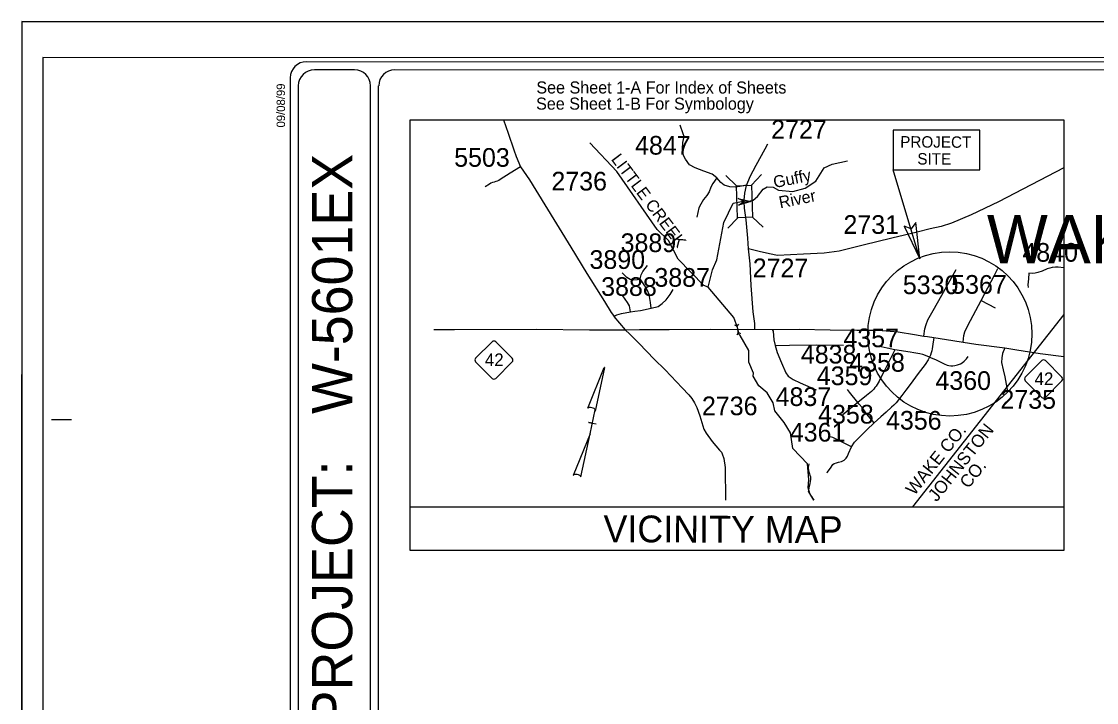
# Model space of a CAD drawing. Extents: x 2110629 to 2114002, y 669321 to 671542.
# Drawn here: x 2110629 to 2111780, y 670813 to 671542 of the extents above; entities that cross this region are included whole.
import ezdxf

# ---------------------------------------------------------------- set-up
doc = ezdxf.new("R2010")
doc.units = 0
for name, color, linetype in [('Default', 7, 'Continuous'), ('Default Symbol Cogo Number', 7, 'Continuous'), ('Exist Building', 7, 'Continuous'), ('Exist Building Leader', 7, 'Continuous'), ('Exist Other Culture Area Outline', 7, 'Continuous'), ('Exist Roads Curbs', 7, 'Continuous'), ('Exist Roads Curbs Text', 7, 'Continuous'), ('Exist Roads EOP Other Text', 7, 'Continuous'), ('Exist Structure Minor Catch Basin', 7, 'Continuous'), ('Exist Structure Minor Footbridge', 7, 'Continuous'), ('Exist Utilities Telephone Test Hole SUE LOS A Text', 7, 'Continuous'), ('Exist Utilities TV Hand Hole CELL', 7, 'Continuous'), ('Exist Utilities Water Test Hole SUE LOS A Text', 7, 'Continuous')]:
    doc.layers.add(name, color=color, linetype=linetype)

msp = doc.modelspace()

# ---------------------------------------------------------------- linework, layer by layer
at = {"layer": 'Default'}
for p, q in [((2111383, 671377.1), (2111394.4, 671366.3)), ((2111421.2, 671378.3), (2111410.5, 671366.8)), ((2111395.8, 671332.1), (2111385.1, 671320.7)), ((2111411.5, 671332.6), (2111422.9, 671321.9)), ((2111392.5, 671217.3), (2111395, 671215.9)), ((2111396.6, 671218.3), (2111395, 671215.9)), ((2111395, 671215.9), (2111396.8, 671209.2)), ((2111395.2, 671206.8), (2111396.8, 671209.2)), ((2111399.3, 671207.8), (2111396.8, 671209.2))]:
    msp.add_line(p, q, dxfattribs=at)
for points in [[(2111364.3, 671257.6), (2111359.4, 671259.5), (2111332, 671287.6), (2111321.7, 671307.6), (2111309.7, 671319.3), (2111266.2, 671381.5), (2111237.4, 671412.2)], [(2111390.9, 671347.7), (2111398.2, 671349.2), (2111399.9, 671349.4), (2111402.8, 671349.3), (2111404.4, 671349.1), (2111412.4, 671350.9), (2111417, 671354.7), (2111423, 671362.5), (2111427.4, 671365.1), (2111433.7, 671364.8), (2111439.3, 671361.6), (2111454.9, 671360.2), (2111468.2, 671363.7), (2111479.4, 671371.1), (2111488.2, 671385.6), (2111496.8, 671389.5), (2111513.2, 671392.8)], [(2111402.8, 671349.3), (2111402.8, 671351), (2111403.4, 671358.5), (2111405.1, 671366.6)], [(2111364.3, 671257.6), (2111368.7, 671276.1), (2111373.4, 671287), (2111380.8, 671327.1), (2111390.9, 671347.7)], [(2111477.2, 671029.9), (2111472.9, 671036.8), (2111471.3, 671042.9), (2111471.8, 671052), (2111470.5, 671068.8), (2111455, 671085), (2111452.3, 671102), (2111445.5, 671113), (2111435.5, 671125.3), (2111433.9, 671133.9), (2111427.5, 671144.8), (2111418.4, 671152), (2111412.4, 671162.4), (2111412.6, 671165.8), (2111407.8, 671177.5), (2111407.6, 671190.1), (2111398.6, 671206), (2111396.8, 671207.7), (2111396.4, 671208.7), (2111396.3, 671210.8), (2111395.9, 671212.5), (2111395.4, 671214.5), (2111391.8, 671225.2), (2111364.3, 671257.6)], [(2111471.9, 671068.5), (2111471.5, 671067), (2111471.2, 671065.1), (2111471.1, 671064), (2111471.5, 671061.4), (2111472, 671060), (2111472.6, 671058.1), (2111473.2, 671056.6), (2111473.7, 671054.9), (2111473.6, 671052.2), (2111473.3, 671049.8), (2111473, 671047.6), (2111472.6, 671045.7), (2111472, 671043.3), (2111471.5, 671039.9), (2111471.4, 671039.7), (2111471.8, 671037.9), (2111472.6, 671036.8), (2111473.8, 671035.1), (2111475.1, 671033.6), (2111476, 671031.9), (2111477.2, 671029.9)]]:
    msp.add_lwpolyline(points, dxfattribs=at)
for points in [[(2111410.5, 671366.8), (2111411.5, 671332.6), (2111395.5, 671332.1), (2111394.4, 671366.3)], [(2111396.2, 671352.6), (2111409.7, 671349.5), (2111396.5, 671345.4), (2111402.8, 671349.3)]]:
    msp.add_lwpolyline(points, close=True, dxfattribs=at)
at = {"layer": 'Default Symbol Cogo Number'}
for p, q in [((2111590.8, 671288.1), (2111562.2, 671383.3)), ((2111745, 671031.5), (2111745, 671028.9)), ((2111045, 671022.6), (2111745, 671022.6))]:
    msp.add_line(p, q, dxfattribs=at)
msp.add_lwpolyline([(2111745, 671028.9), (2111745, 670975.8), (2111045, 670975.8), (2111045, 671436.7), (2111745, 671436.7), (2111745, 671031.5)], dxfattribs=at)
for points in [[(2111562.2, 671383.3), (2111655.1, 671383.3), (2111655.1, 671425.9), (2111562.2, 671425.9)], [(2111573.9, 671322.9), (2111590.8, 671288.1), (2111586.7, 671326.8), (2111581.5, 671320.2)]]:
    msp.add_lwpolyline(points, close=True, dxfattribs=at)
msp.add_circle((2111622.9, 671207.7), 87.9, dxfattribs=at)
at = {"layer": 'Exist Building'}
for p, q in [((2111115.2, 671181.6), (2111132.9, 671199.3)), ((2111136.7, 671199.3), (2111154.4, 671181.6)), ((2111114.4, 671179.9), (2111114.4, 671179.9)), ((2111132.9, 671160.1), (2111115.2, 671177.8)), ((2111154.4, 671177.8), (2111136.7, 671160.1)), ((2111703.7, 671161.4), (2111721.5, 671179.1)), ((2111725.3, 671179.1), (2111743, 671161.3)), ((2111702.9, 671159.6), (2111702.9, 671159.6)), ((2111721.4, 671139.8), (2111703.7, 671157.6)), ((2111743, 671157.5), (2111725.2, 671139.8))]:
    msp.add_line(p, q, dxfattribs=at)
for centre, start, end in [((2111134.8, 671197.4), 93.1291, 134.9188), ((2111134.8, 671197.4), 44.9188, 92.9952), ((2111117.1, 671179.7), 134.9188, 176.3258), ((2111152.5, 671179.7), 1.8482, 44.9188), ((2111117.1, 671179.7), 176.4784, 224.9188), ((2111152.5, 671179.7), 314.9188, 1.6571), ((2111723.4, 671177.2), 93.1291, 134.9188), ((2111723.4, 671177.2), 44.9188, 92.9952), ((2111134.8, 671162), 224.9188, 264.9661), ((2111134.8, 671162), 265.1003, 314.9188), ((2111705.6, 671159.5), 134.9188, 176.3258), ((2111705.6, 671159.5), 176.4784, 224.9188), ((2111741.1, 671159.4), 1.8482, 44.9188), ((2111741.1, 671159.4), 314.9188, 1.6571), ((2111723.3, 671141.7), 224.9188, 264.9661), ((2111723.3, 671141.7), 265.1003, 314.9188)]:
    msp.add_arc(centre, 2.69, start, end, dxfattribs=at)
at = {"layer": 'Exist Building Leader'}
for points in [[(2111070.3, 671212.5), (2111092.6, 671212.3), (2111180.2, 671212.6), (2111237.2, 671212.2), (2111275.3, 671212.2)], [(2111275.3, 671212.2), (2111290.6, 671212.3), (2111322.3, 671212.3), (2111367.2, 671212.6), (2111395.9, 671212.5), (2111414.2, 671212.6)], [(2111414.2, 671212.6), (2111432.7, 671212.5)], [(2111432.7, 671212.5), (2111461.6, 671212.6), (2111494.7, 671212.1), (2111523.3, 671211.8), (2111546.3, 671211.7), (2111567.6, 671209.8)], [(2111567.6, 671209.8), (2111585, 671207.1), (2111595.1, 671205.4)], [(2111595.1, 671205.4), (2111599.1, 671204.8), (2111605.9, 671203.8)], [(2111605.9, 671203.8), (2111626.3, 671200.7), (2111637.1, 671199)], [(2111637.1, 671199), (2111650.9, 671196.8), (2111681.8, 671192.7)], [(2111681.8, 671192.7), (2111694.7, 671190.7), (2111719.5, 671186.6), (2111745, 671183.4)]]:
    msp.add_lwpolyline(points, dxfattribs=at)
at = {"layer": 'Exist Roads Curbs'}
for q in [(2110628.9, 669648.7), (2113527.8, 671541.5)]:
    msp.add_line((2110629.2, 671542), q, dxfattribs=at)
at = {"layer": 'Exist Roads Curbs Text'}
for p, q in [((2111163.2, 671386.5), (2111152.3, 671379.9)), ((2111656.5, 671243.4), (2111671.3, 671235.6))]:
    msp.add_line(p, q, dxfattribs=at)
for points in [[(2111144.9, 671436.7), (2111149.9, 671422.6), (2111156.1, 671404.6), (2111158.7, 671397.5), (2111163.2, 671386.5)], [(2111373.5, 671374.7), (2111368.3, 671378.7), (2111359.6, 671381.9), (2111350.2, 671385.4), (2111344.3, 671388.8), (2111339.8, 671394.7), (2111337.6, 671398.7), (2111336.7, 671405.6), (2111337, 671412.7), (2111338.3, 671418.8), (2111337.5, 671421.7), (2111334.2, 671431)], [(2111405.1, 671366.6), (2111409.2, 671376.3), (2111415.7, 671388.4), (2111425.2, 671405.7), (2111428.2, 671411)], [(2111152.3, 671379.9), (2111141.5, 671372.8), (2111140, 671372), (2111138.3, 671371.2), (2111136.7, 671370.7), (2111135, 671370.2), (2111133.2, 671369.6), (2111131.5, 671368.9), (2111130, 671368), (2111125.4, 671365.1)], [(2111163.2, 671386.5), (2111172.8, 671372.5), (2111189.4, 671345.7), (2111217.1, 671300.4), (2111234.4, 671272.3), (2111253, 671242.4), (2111260.2, 671230.7), (2111263.7, 671226)], [(2111745, 671385.4), (2111675, 671349), (2111645.8, 671335.3), (2111624.6, 671326.2), (2111613.5, 671322.8), (2111601.8, 671320.1), (2111587.8, 671316.6), (2111560.7, 671310), (2111530.2, 671302.5), (2111504.3, 671296.4), (2111488.5, 671294.1), (2111466.4, 671292.9), (2111438.3, 671291.7)], [(2111373.5, 671374.7), (2111369.1, 671368.5), (2111367, 671364.6), (2111365.2, 671359.6), (2111362.8, 671355.7), (2111359.2, 671351.6), (2111356.2, 671346.6), (2111354.1, 671342.5), (2111352, 671332.7)], [(2111405.1, 671366.6), (2111403.3, 671366.5), (2111398.2, 671365.4), (2111393.1, 671364.8), (2111387.2, 671365.2), (2111381.4, 671367), (2111377.9, 671369.7), (2111373.5, 671374.7)], [(2111407.4, 671298.6), (2111406.5, 671310.3), (2111404.9, 671329.9), (2111403.2, 671342.3), (2111402.8, 671349.3)], [(2111438.3, 671291.7), (2111429.8, 671293.3), (2111418.9, 671296), (2111407.4, 671298.6)], [(2111414.2, 671212.6), (2111414, 671218.9), (2111412.5, 671231.2), (2111410.3, 671259.4), (2111409.2, 671282.7), (2111407.4, 671298.6)], [(2111291.3, 671266.6), (2111288, 671265.5), (2111284.3, 671265.3), (2111280.7, 671265.9), (2111277.2, 671268.1), (2111272.2, 671273.1)], [(2111291.3, 671266.6), (2111292.5, 671271.1), (2111294.3, 671274.4), (2111299.2, 671281)], [(2111595.1, 671205.4), (2111596.2, 671213), (2111597.5, 671217.7), (2111599.5, 671222.7), (2111603.6, 671230.4), (2111611.1, 671243.5), (2111629.7, 671276.8)], [(2111656.5, 671243.4), (2111670.6, 671270.4), (2111674.4, 671277.7)], [(2111745, 671278.4), (2111739.1, 671279), (2111738.3, 671279.1), (2111736, 671279), (2111732.6, 671278.7), (2111730, 671278.2), (2111727.2, 671277.3), (2111721.8, 671274.9), (2111717.3, 671273.3), (2111714.3, 671272.7), (2111711, 671272.4), (2111707.6, 671272.6)], [(2111303.2, 671235.2), (2111302.4, 671241.3), (2111301.1, 671249.9), (2111299.2, 671254.1), (2111296.2, 671259.2), (2111291.3, 671266.6)], [(2111707.6, 671272.6), (2111707, 671266.8), (2111706.6, 671260.3), (2111706.7, 671257.3)], [(2111303.2, 671235.2), (2111310.5, 671237.2), (2111314.8, 671240.1), (2111319.2, 671244), (2111323.4, 671249.8), (2111326.6, 671255.4)], [(2111281, 671231.3), (2111279.9, 671237.7), (2111277.8, 671241.4), (2111272.7, 671248.6)], [(2111637.1, 671199), (2111638, 671206.1), (2111639.1, 671210.1), (2111640.7, 671213.7), (2111645.2, 671222), (2111656.5, 671243.4)], [(2111263.2, 671226.2), (2111266.4, 671228.1), (2111271.4, 671229.7), (2111281, 671231.3)], [(2111281, 671231.3), (2111285.6, 671232), (2111291.8, 671232.9), (2111303.2, 671235.2)], [(2111263.2, 671226.2), (2111275.3, 671212.2)], [(2111275.3, 671212.2), (2111280.3, 671207.4), (2111290.4, 671197.5), (2111306.4, 671180.8), (2111318, 671169.1), (2111336.3, 671150), (2111343.3, 671142.6), (2111346.7, 671138.4), (2111349.7, 671133.8), (2111352.1, 671128.9), (2111355.2, 671119.9), (2111359.4, 671105.9), (2111362, 671101.5), (2111368.6, 671092.7), (2111376.4, 671083.4), (2111378.3, 671081.1), (2111379.3, 671079.4), (2111381.1, 671074.3), (2111382.4, 671064.8), (2111382.6, 671029.9)], [(2111432.7, 671212.5), (2111433.9, 671210.5), (2111434.6, 671201.4), (2111435.8, 671195.2)], [(2111605.9, 671203.8), (2111604.5, 671194.4), (2111604.1, 671191.8), (2111603.6, 671189.6), (2111603, 671187.3), (2111602.1, 671184.8), (2111601.2, 671182.7)], [(2111435.8, 671195.2), (2111451.3, 671195.8), (2111480.7, 671196), (2111509, 671195.8)], [(2111435.8, 671195.2), (2111437.9, 671187.7), (2111442.7, 671176.9), (2111447.4, 671165.9), (2111449.7, 671162.3), (2111455.1, 671158.8), (2111462.5, 671155.4), (2111479.9, 671147.9)], [(2111563.9, 671190.8), (2111555.7, 671192.6), (2111549.5, 671193.8), (2111548.2, 671194.1)], [(2111681.8, 671192.7), (2111679.5, 671186.7), (2111678.6, 671182.2), (2111678.4, 671177.2), (2111680.2, 671169.3), (2111681.9, 671161.6), (2111684.6, 671146.1)], [(2111564.2, 671190.8), (2111558.5, 671179.2), (2111553.2, 671169.1), (2111549.5, 671161.9), (2111547.1, 671157), (2111545.2, 671153.7), (2111544, 671151.8), (2111542.7, 671150.2), (2111541.4, 671148.5), (2111538.9, 671146), (2111533.7, 671141.7), (2111524.4, 671134.3)], [(2111601.2, 671182.7), (2111599.7, 671180), (2111596.4, 671175), (2111589, 671165.2), (2111580.3, 671153.5), (2111575.8, 671147.6), (2111571.6, 671141.9), (2111567.8, 671137.1), (2111565.6, 671134.1), (2111562.9, 671131.3), (2111560.4, 671129.2), (2111554.8, 671124), (2111549, 671118.8), (2111542, 671112.4)], [(2111601.2, 671182.7), (2111596.8, 671184.7), (2111593.9, 671185.6), (2111590.7, 671186.4), (2111584.4, 671187.6), (2111580.5, 671188.3), (2111563.9, 671190.8)], [(2111601.2, 671182.7), (2111607.5, 671180.2), (2111612.6, 671177.7), (2111616.7, 671175.7), (2111620, 671174.3), (2111621.9, 671173.8), (2111623.9, 671173.5), (2111626, 671173.5), (2111628.3, 671173.8), (2111631.2, 671174.6), (2111634.2, 671175.8), (2111636, 671176.7), (2111638.2, 671178.5), (2111640.6, 671181), (2111642.7, 671183.7)], [(2111524.4, 671134.3), (2111515.4, 671145.2), (2111513.3, 671148.2)], [(2111524.4, 671134.3), (2111518.6, 671129.7), (2111512.5, 671124.6), (2111508.2, 671121.2)], [(2111542, 671112.4), (2111534.2, 671121.7), (2111528.9, 671128.8), (2111525.7, 671132.6), (2111524.4, 671134.3)], [(2111517.5, 671086.7), (2111521, 671091.9), (2111534.1, 671105), (2111542, 671112.4)], [(2111517.5, 671086.7), (2111497.6, 671096.8), (2111494.8, 671097.4)], [(2111491.4, 671059.2), (2111491.6, 671059.4), (2111495.1, 671064.1), (2111497.8, 671067.9), (2111499.2, 671068.9), (2111501.6, 671069.9), (2111503.8, 671070.4), (2111507.1, 671071.3), (2111509.7, 671072.7), (2111511.9, 671074.6), (2111513.5, 671076.7), (2111514.6, 671079.6), (2111517.5, 671086.7)]]:
    msp.add_lwpolyline(points, dxfattribs=at)
at = {"layer": 'Exist Roads EOP Other Text'}
msp.add_lwpolyline([(2110651.3, 669687.3), (2113519.8, 669686.8), (2113520.1, 671502.9), (2110651.6, 671503.4)], close=True, dxfattribs=at)
at = {"layer": 'Exist Structure Minor Catch Basin'}
for p, q in [((2111002.4, 669717.5), (2111002.7, 671473.1)), ((2111011.1, 670035.9), (2111011.3, 671473.1)), ((2110661, 671116), (2110682.5, 671116)), ((2110661, 671116), (2110682.5, 671116))]:
    msp.add_line(p, q, dxfattribs=at)
for points in [[(2113481.4, 671498.5), (2110933.9, 671499)], [(2110916.7, 671481.8), (2110916.4, 669708.9)], [(2110916.7, 671481.8), (2110916.4, 669708.9)], [(2110985.5, 671490.3), (2110942.5, 671490.4)], [(2113472.7, 671489.9), (2111028.6, 671490.3)], [(2110925.3, 671473.2), (2110925, 669717.5)]]:
    msp.add_lwpolyline(points, dxfattribs=at)
for centre, start, end in [((2110933.9, 671481.8), 89.9903, 179.9903), ((2110942.5, 671473.2), 89.9903, 179.9903), ((2110985.5, 671473.2), 359.9903, 89.9903), ((2111028.6, 671473.2), 89.9903, 179.9903)]:
    msp.add_arc(centre, 17.2, start, end, dxfattribs=at)
at = {"layer": 'Exist Structure Minor Footbridge'}
msp.add_line((2111745, 671228.6), (2111583.1, 671022.6), dxfattribs=at)
at = {"layer": 'Exist Utilities TV Hand Hole CELL'}
for p, q in [((2111235.2, 671128.2), (2111252.9, 671171.8)), ((2111253, 671171.8), (2111243, 671125)), ((2111253, 671171.8), (2111252.9, 671171.8)), ((2111253, 671171.8), (2111252.9, 671171.8)), ((2111237.8, 671100.8), (2111243.3, 671126.4)), ((2111243, 671125), (2111243.2, 671126.4)), ((2111236.3, 671113), (2111236.2, 671113)), ((2111236.3, 671113), (2111244.2, 671111.3)), ((2111239.8, 671112.2), (2111236.3, 671113)), ((2111237.8, 671100.8), (2111219.7, 671056.3)), ((2111228, 671054.8), (2111237.8, 671100.8))]:
    msp.add_line(p, q, dxfattribs=at)
for centre, start_param, end_param in [((2111239.1, 671126.8), 0.216388, 2.908219), ((2111223.9, 671055.3), 0.201328, 3.141593)]:
    msp.add_ellipse(centre, major_axis=(4.13, -0.91), ratio=0.461098, start_param=start_param, end_param=end_param, dxfattribs=at)
at = {"layer": 'Exist Utilities Water Test Hole SUE LOS A Text'}
msp.add_lwpolyline([(2113527.8, 671541.5), (2110629.2, 671542), (2110628.9, 669648.7), (2113527.5, 669648.2)], close=True, dxfattribs=at)

# ---------------------------------------------------------------- texts
at = {"layer": 'Default'}
for s, height, rotation, p in [('LITTLE CREEK', 12.762, 306.9522, (2111259.7, 671394.5)), ('Guffy', 12.76, 11.4692, (2111435.3, 671363.7)), ('River', 12.76, 11.4692, (2111441.3, 671342))]:
    msp.add_text(s, height=height, rotation=rotation, dxfattribs=at).set_placement(p)
at = {"layer": 'Default Symbol Cogo Number'}
for s, height, rotation, p in [('PROJECT', 12.2, 359.7111, (2111569.8, 671407.2)), ('SITE', 12.2, 359.7111, (2111588.1, 671389)), ('VICINITY MAP', 28.714, 359.7803, (2111252, 670984.8))]:
    msp.add_text(s, height=height, rotation=rotation, dxfattribs=at).set_placement(p)
at = {"layer": 'Exist Building'}
for p in [(2111125.1, 671173.3), (2111713.7, 671153)]:
    msp.add_text('42', height=13.5, rotation=359.9188, dxfattribs=at).set_placement(p)
at = {"layer": 'Exist Other Culture Area Outline'}
for s, p in [('2727', (2111431.6, 671416.6)), ('4847', (2111285.9, 671399.6)), ('5503', (2111092.2, 671386.6)), ('2736', (2111196.3, 671361.2)), ('2731', (2111509, 671314.8)), ('3889', (2111270.4, 671295.3)), ('3890', (2111237.1, 671277.3)), ('4840', (2111700.6, 671285)), ('2727', (2111411.9, 671268.4)), ('3887', (2111306.6, 671258.2)), ('3888', (2111249.6, 671248.4)), ('5330', (2111572.6, 671250.3)), ('5367', (2111624.4, 671250.7)), ('4357', (2111509, 671193.5)), ('4838', (2111463.4, 671176)), ('4358', (2111515.3, 671167.3)), ('4359', (2111480.5, 671152.9)), ('4360', (2111607.5, 671147.8)), ('4837', (2111436.4, 671130.6)), ('2735', (2111677.1, 671127.6)), ('2736', (2111357.5, 671120.7)), ('4358', (2111481.9, 671111.8)), ('4356', (2111554.6, 671105.3)), ('4361', (2111451.6, 671092.5))]:
    msp.add_text(s, height=20, rotation=359.932, dxfattribs=at).set_placement(p)
at = {"layer": 'Exist Structure Minor Catch Basin'}
for s, height, rotation, p in [('09/08/99', 9.04, 89.9903, (2110911.1, 671428.6)), ('See Sheet 1-A For Index of Sheets', 12.909, 359.9903, (2111180.2, 671465)), ('See Sheet 1-B For Symbology', 12.909, 359.9903, (2111179.9, 671447.7)), ('W-5601EX', 43.03, 89.9903, (2110983.1, 671122.1)), ('TIP PROJECT:', 43.031, 89.9903, (2110983, 670682.2))]:
    msp.add_text(s, height=height, rotation=rotation, dxfattribs=at).set_placement(p)
at = {"layer": 'Exist Structure Minor Footbridge'}
for s, p in [('JOHNSTON ', (2111608.8, 671027.3)), ('WAKE CO.', (2111585, 671034)), ('CO.', (2111642.8, 671041.4))]:
    msp.add_text(s, height=13.5, rotation=51.2991, dxfattribs=at).set_placement(p)
at = {"layer": 'Exist Utilities Telephone Test Hole SUE LOS A Text'}
msp.add_text('         WAKE COUNTY         ', height=51.637, rotation=359.9903, dxfattribs=at).set_placement((2111490, 671283.3))

doc.saveas('drawing.dxf')
